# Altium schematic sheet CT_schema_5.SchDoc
size 405 x 321 mm
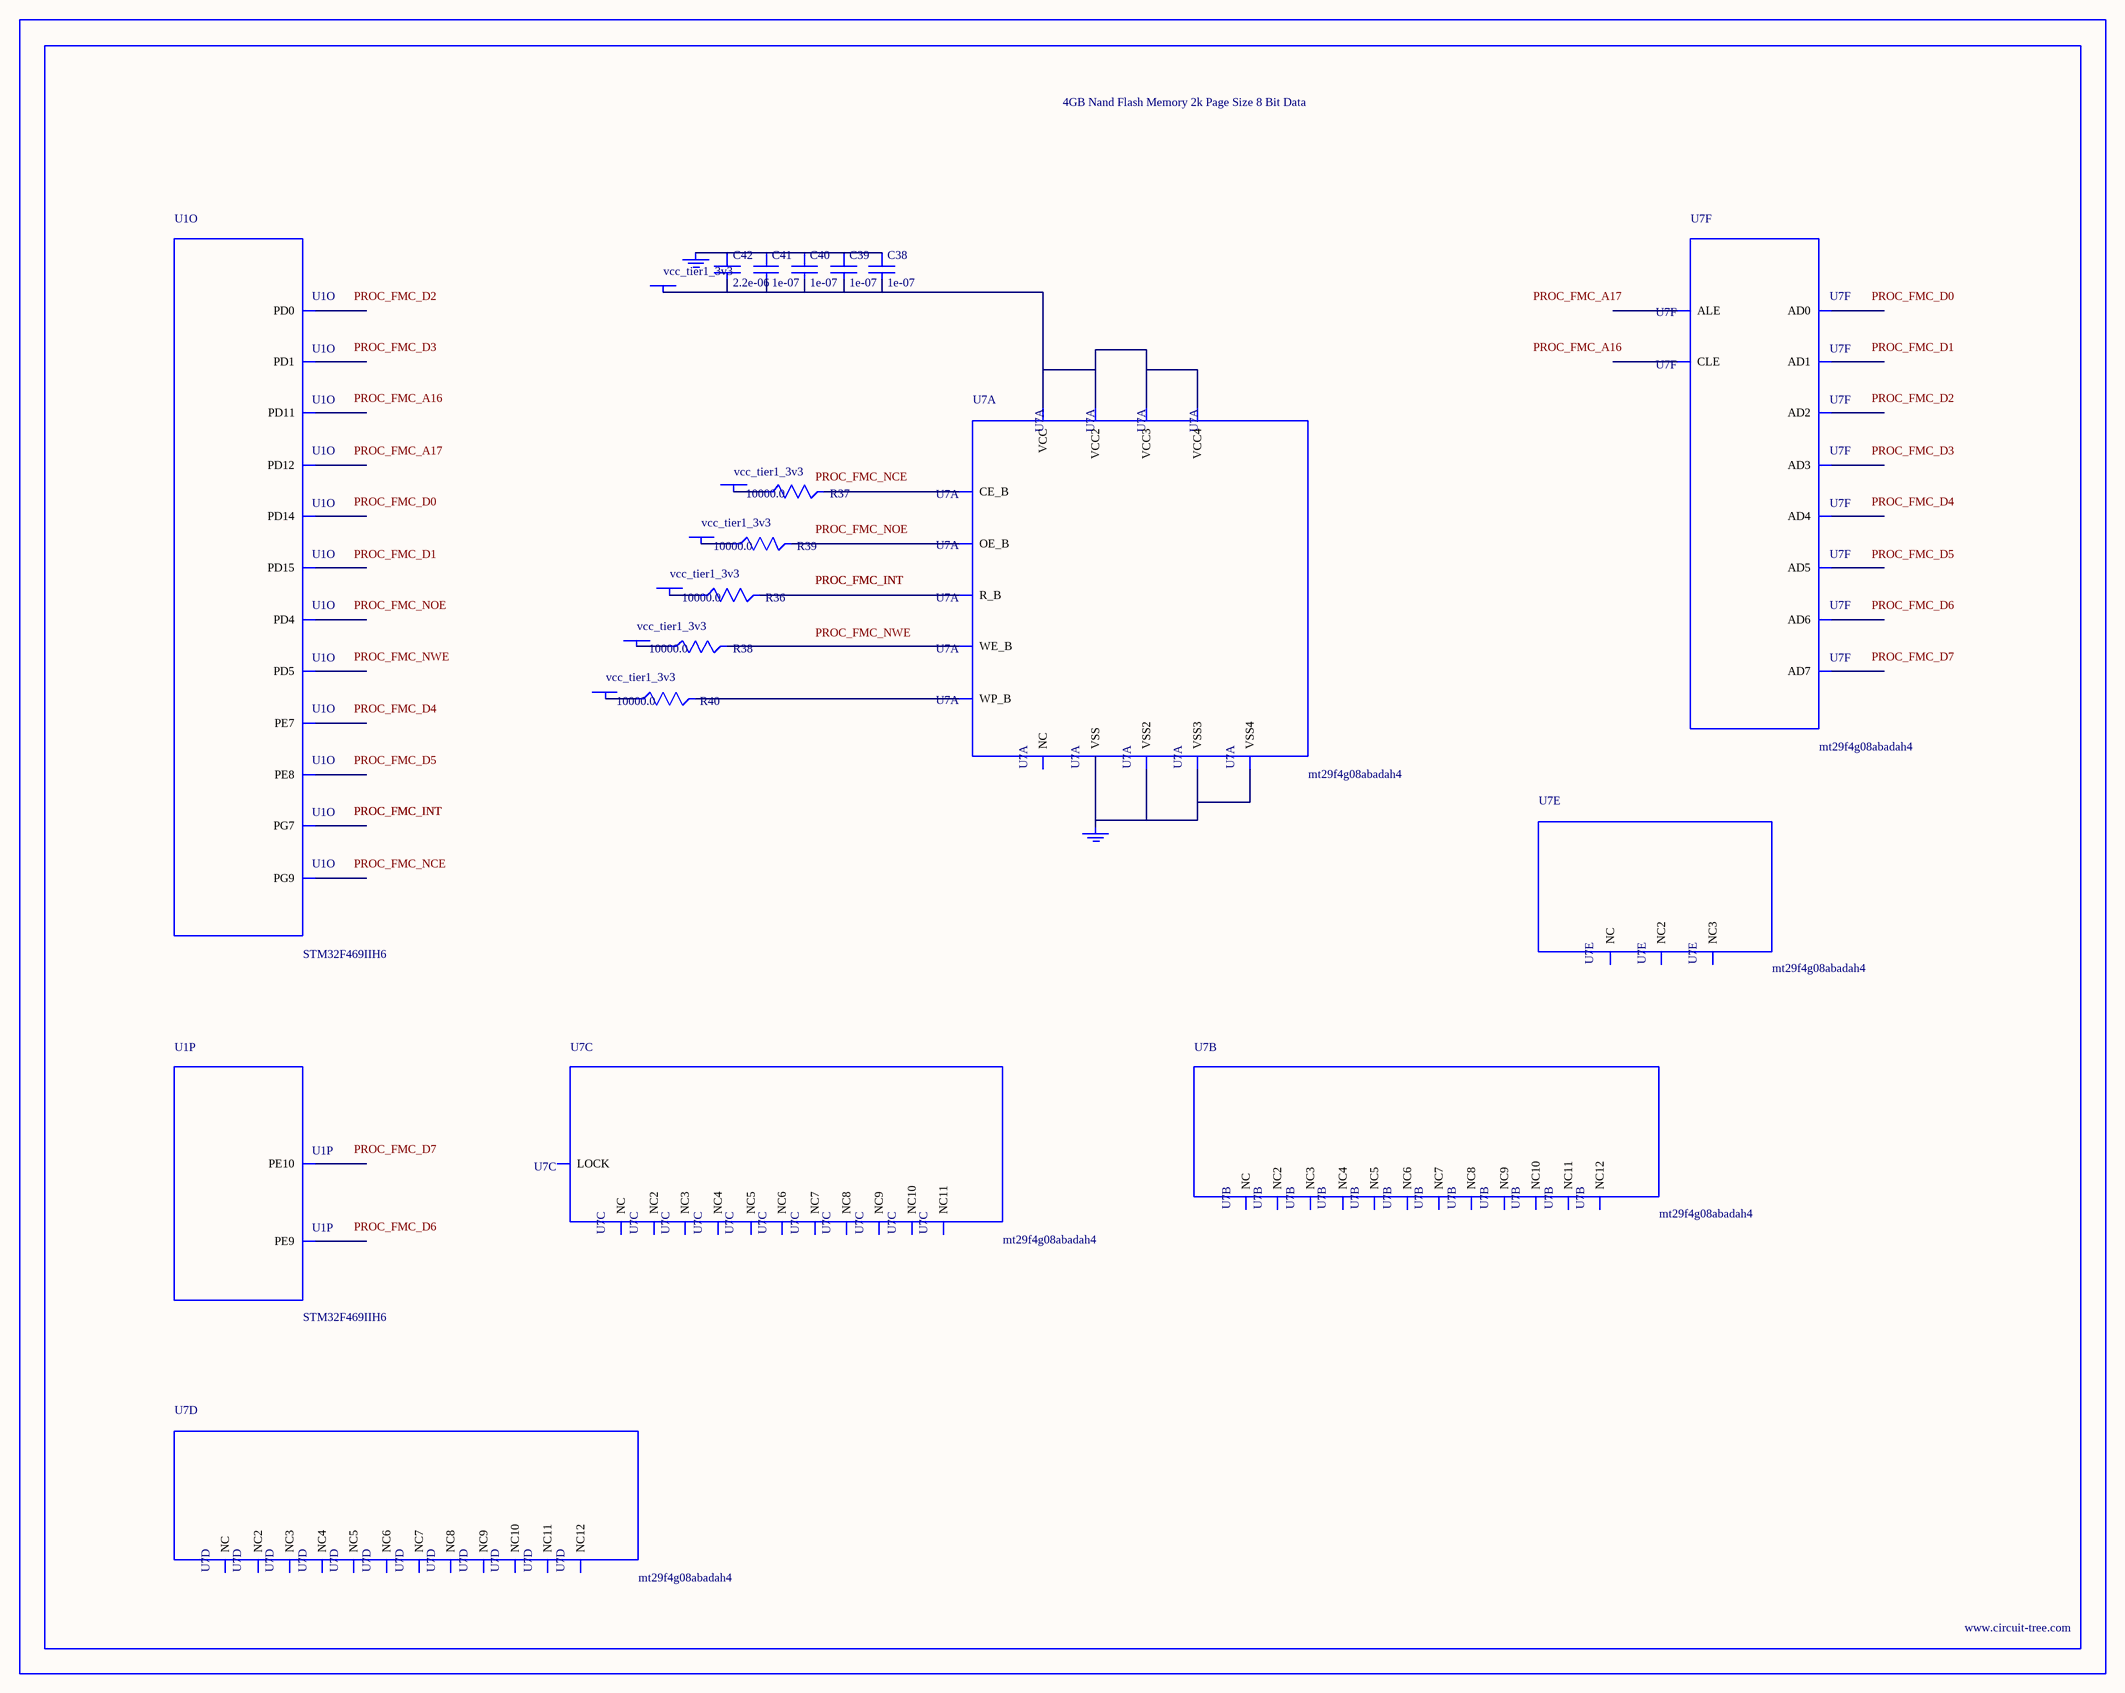
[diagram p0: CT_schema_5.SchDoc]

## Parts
BORDER4  (no value)
C38  1e-07  [C0402]
C39  1e-07  [C0402]
C40  1e-07  [C0402]
C41  1e-07  [C0402]
C42  2.2e-06  [C0603]
GND_INSTANCE_4_0  (no value)
GND_INSTANCE_4_1  (no value)
POWER_INSTANCE_4_0  vcc_tier1_3v3
POWER_INSTANCE_4_1  vcc_tier1_3v3
POWER_INSTANCE_4_2  vcc_tier1_3v3
POWER_INSTANCE_4_3  vcc_tier1_3v3
POWER_INSTANCE_4_4  vcc_tier1_3v3
POWER_INSTANCE_4_5  vcc_tier1_3v3
R36  10000.0  [R0603]
R37  10000.0  [R0603]
R38  10000.0  [R0603]
R39  10000.0  [R0603]
R40  10000.0  [R0603]
U1  STM32F469IIH6  [UFBGA176]  (parts O,P of 17)
U7  mt29f4g08abadah4  [VFBGA-63]  (parts A,B,C,D,E,F of 6)

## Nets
NetC38_1: C38.1 C39.1 C40.1 C41.1 C42.1 GND_INSTANCE_4_0.0(GND)
NetC38_2: C38.2 C39.2 C40.2 C41.2 C42.2 POWER_INSTANCE_4_0.0(PWR) U7.D3(VCC) U7.G4(VCC2) U7.H8(VCC3) U7.J6(VCC4)
NetGND_INSTANCE_4_1_0: GND_INSTANCE_4_1.0(GND) U7.C5(VSS) U7.F7(VSS2) U7.K3(VSS3) U7.K8(VSS4)
NetPOWER_INSTANCE_4_1_0: POWER_INSTANCE_4_1.0(PWR) R36.1
NetPOWER_INSTANCE_4_2_0: POWER_INSTANCE_4_2.0(PWR) R37.1
NetPOWER_INSTANCE_4_3_0: POWER_INSTANCE_4_3.0(PWR) R38.1
NetPOWER_INSTANCE_4_4_0: POWER_INSTANCE_4_4.0(PWR) R39.1
NetPOWER_INSTANCE_4_5_0: POWER_INSTANCE_4_5.0(PWR) R40.1
NetR36_2: R36.2 U7.C8(R_B)
NetR37_2: R37.2 U7.C6(CE_B)
NetR38_2: R38.2 U7.C7(WE_B)
NetR39_2: R39.2 U7.D4(OE_B)
NetR40_2: R40.2 U7.C3(WP_B)

Not connected (* = marked no-connect by the designer): U1 B12(PD0) C10(PG9) C11(PD5) C12(PD1) D10(PD4) J14(PG7) L14(PD15) M14(PD14) N13(PD12) N14(PD11) P8(PE8) P9(PE9) R8(PE7) R9(PE10); U7 A1(NC) A2(NC3) A9(NC4) A10(NC2) B1(NC5) B9(NC7) B10(NC6) C4(ALE) D5(CLE) D6(NC8) D7(NC9) D8(NC10) E3(NC11) E4(NC12) E5(NC) E6(NC2) E7(NC3) E8(NC4) F3(NC5) F4(NC6) F5(NC7) F6(NC8) F8(NC9) G3(NC) G5(LOCK) G6(NC10) G7(NC11) G8(NC) H3(NC2) H4(AD0) H5(NC3) H6(NC4) H7(NC5) J3(NC6) J4(AD1) J5(NC7) J7(AD5) J8(AD7) K4(AD2) K5(AD3) K6(AD4) K7(AD6) L1(NC8) L2(NC10) L9(NC11) L10(NC9) M1(NC12) M2(NC2) M9(NC3) M10(NC)

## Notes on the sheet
- Labels drawn without touching a wire or pin: PROC_FMC_A16, PROC_FMC_A17, PROC_FMC_D0, PROC_FMC_D1, PROC_FMC_D2, PROC_FMC_D3, PROC_FMC_D4, PROC_FMC_D5, PROC_FMC_D6, PROC_FMC_D7, PROC_FMC_NCE, PROC_FMC_NOE, PROC_FMC_NWE

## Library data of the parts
BORDER4 = BORDER_PAGE4
C38-C41 = C0402C104K3RACTU
C42 = C0603C225K8RACTU
GND_INSTANCE_4_0 GND_INSTANCE_4_1 = GND
POWER_INSTANCE_4_0-POWER_INSTANCE_4_5 = PWR
R36-R40 = RC0603JR-0710KL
